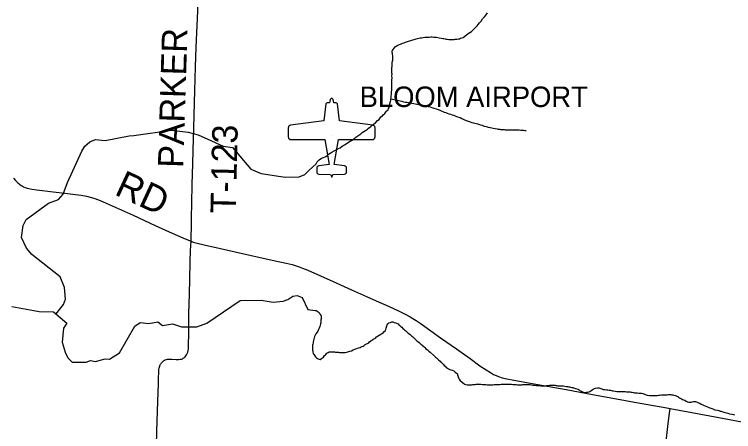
# Model space of a CAD drawing. Extents: x -13.9 to 69.1, y -25.2 to 26.1.
# Drawn here: x 2.896 to 4.329, y 15.614 to 16.445 of the extents above; entities that cross this region are included whole.
import ezdxf

# ---------------------------------------------------------------- set-up
doc = ezdxf.new("R2010")
doc.units = 0
for name, color, linetype in [('GM_X_Airport_Class_3', 7, 'Continuous'), ('GM_X_Airport_Location_Class_3', 7, 'Continuous'), ('GM_X_Airport_Text_Class_3', 7, 'Continuous'), ('GM_X_County_Road', 7, 'Continuous'), ('GM_X_County_Road_Text', 7, 'Continuous'), ('GM_X_Minor_River', 7, 'Continuous'), ('GM_X_Township_Road', 7, 'Continuous'), ('GM_X_Township_Road_Text', 7, 'Continuous')]:
    doc.layers.add(name, color=color, linetype=linetype)

msp = doc.modelspace()

# ---------------------------------------------------------------- linework, layer by layer
at = {"layer": 'GM_X_Airport_Class_3'}
for points in [[(3.5282, 16.2781), (3.5269, 16.2775), (3.5255, 16.2753), (3.5245, 16.272), (3.524, 16.2687), (3.5194, 16.2687), (3.5177, 16.2681), (3.5168, 16.2666), (3.5123, 16.2332), (3.4463, 16.2242), (3.4434, 16.2228), (3.4423, 16.2215), (3.4414, 16.2182), (3.4414, 16.2018), (3.4424, 16.1982), (3.4452, 16.196), (3.5148, 16.1955), (3.5229, 16.1458), (3.5024, 16.1433), (3.5012, 16.143), (3.4994, 16.1413), (3.4989, 16.1401), (3.4987, 16.131), (3.4989, 16.1296), (3.5004, 16.1274), (3.5029, 16.1265), (3.526, 16.1264), (3.5282, 16.1206)], [(3.5282, 16.1206), (3.5304, 16.1264), (3.5535, 16.1265), (3.556, 16.1274), (3.5575, 16.1296), (3.5577, 16.131), (3.5575, 16.1401), (3.557, 16.1413), (3.5551, 16.143), (3.554, 16.1433), (3.5335, 16.1458), (3.5416, 16.1955), (3.6112, 16.196), (3.614, 16.1982), (3.615, 16.2018), (3.615, 16.2182), (3.6141, 16.2215), (3.613, 16.2228), (3.6101, 16.2242), (3.5441, 16.2332), (3.5396, 16.2666), (3.5387, 16.2681), (3.537, 16.2687), (3.5324, 16.2687), (3.5319, 16.272), (3.5309, 16.2753), (3.5295, 16.2775), (3.5282, 16.2781)]]:
    msp.add_lwpolyline(points, dxfattribs=at)
at = {"layer": 'GM_X_Airport_Location_Class_3'}
msp.add_line((3.5282, 16.2037), (3.5282, 16.2037), dxfattribs=at)
at = {"layer": 'GM_X_County_Road'}
for points in [[(2.8942, 16.119), (2.8984, 16.1143), (2.9033, 16.1096), (2.9065, 16.1066), (2.9096, 16.1042), (2.9123, 16.1026), (2.9145, 16.1014), (2.9178, 16.1001), (2.9215, 16.0988), (2.925, 16.098), (2.9309, 16.0967), (2.9406, 16.0954), (2.9732, 16.0918), (2.9968, 16.0892), (3.0127, 16.0871), (3.0292, 16.0847), (3.0401, 16.0827), (3.0472, 16.0811), (3.0547, 16.0789), (3.0637, 16.0757), (3.073, 16.072), (3.0909, 16.064), (3.1092, 16.0556), (3.1326, 16.045), (3.1769, 16.0249), (3.2105, 16.0096), (3.232, 15.9999), (3.2463, 15.9938), (3.248, 15.9932)], [(3.1791, 15.5865), (3.18, 15.6156), (3.182, 15.6744), (3.183, 15.7095), (3.1834, 15.7226), (3.1836, 15.7309), (3.1839, 15.735), (3.1842, 15.7381), (3.1847, 15.741), (3.1858, 15.745), (3.1868, 15.7472), (3.1875, 15.7487), (3.1885, 15.7501), (3.1895, 15.7515), (3.1907, 15.7528), (3.1919, 15.7539), (3.1934, 15.7552), (3.1951, 15.7563), (3.1966, 15.757), (3.1992, 15.758), (3.2011, 15.7584), (3.2029, 15.7587), (3.2052, 15.7589), (3.2096, 15.7588), (3.2185, 15.7582), (3.2228, 15.7581), (3.2263, 15.7583), (3.229, 15.7588), (3.231, 15.7595), (3.2326, 15.7603), (3.234, 15.7612), (3.2353, 15.7622), (3.2366, 15.7634), (3.238, 15.7651), (3.2393, 15.7671), (3.2406, 15.7697), (3.2415, 15.7725), (3.2423, 15.776), (3.2427, 15.7782), (3.2429, 15.7807), (3.2432, 15.7873), (3.2434, 15.8087), (3.2435, 15.8235), (3.244, 15.8509), (3.2443, 15.8675), (3.2448, 15.8895), (3.2454, 15.9163), (3.2463, 15.9531), (3.2471, 15.9751), (3.248, 15.9932)], [(3.248, 15.9932), (3.252, 15.9917), (3.2605, 15.9894), (3.274, 15.9861), (3.307, 15.9788), (3.3655, 15.9657), (3.4158, 15.9544), (3.4375, 15.9498), (3.4494, 15.9468), (3.4574, 15.9445), (3.4632, 15.9426), (3.4701, 15.94), (3.4809, 15.9354), (3.5309, 15.913), (3.5676, 15.8965), (3.5977, 15.883), (3.6171, 15.8744), (3.6427, 15.8631), (3.6625, 15.854), (3.6762, 15.8474), (3.6846, 15.8429), (3.69, 15.8398), (3.6962, 15.8358), (3.7065, 15.8288), (3.7452, 15.8012), (3.7766, 15.7789), (3.8038, 15.7596), (3.8235, 15.7453), (3.8357, 15.7371), (3.8443, 15.7318), (3.8506, 15.7283), (3.8556, 15.7259), (3.8607, 15.7238), (3.8681, 15.7214), (3.8772, 15.7192), (3.8913, 15.7166), (3.9388, 15.708), (3.995, 15.6982), (4.0478, 15.6884), (4.0958, 15.6797), (4.1317, 15.6732), (4.1961, 15.6617), (4.2024, 15.6605)], [(4.1947, 15.5947), (4.1979, 15.6246), (4.2005, 15.6464), (4.2018, 15.6559), (4.2024, 15.6605)], [(4.2024, 15.6605), (4.2636, 15.6494), (4.317, 15.6394), (4.3382, 15.6355), (4.3562, 15.6321), (4.3666, 15.6305), (4.3784, 15.6293)]]:
    msp.add_lwpolyline(points, dxfattribs=at)
at = {"layer": 'GM_X_Minor_River'}
for points in [[(3.6696, 16.3878), (3.6723, 16.3884), (3.675, 16.3895), (3.6774, 16.3902), (3.6795, 16.3909), (3.6815, 16.3916), (3.6839, 16.3923), (3.6859, 16.393), (3.6879, 16.3933), (3.6899, 16.3941), (3.6923, 16.3947), (3.6943, 16.3955), (3.6967, 16.3962), (3.6991, 16.3969), (3.7015, 16.3972), (3.7042, 16.3979), (3.7072, 16.3982), (3.7102, 16.3985), (3.7136, 16.3992), (3.7184, 16.3995), (3.7221, 16.3995), (3.7254, 16.3998), (3.7285, 16.3998), (3.7315, 16.3997), (3.7342, 16.3997), (3.7369, 16.3993), (3.7396, 16.3989), (3.7426, 16.3981), (3.746, 16.3974), (3.7494, 16.397), (3.7517, 16.3966), (3.7544, 16.3962), (3.7565, 16.3958), (3.7585, 16.3958), (3.7619, 16.395), (3.7642, 16.395), (3.7673, 16.3949), (3.77, 16.3949), (3.772, 16.3949), (3.774, 16.3952), (3.7757, 16.3952), (3.7777, 16.3955), (3.7808, 16.3959), (3.7831, 16.3962), (3.7848, 16.3973), (3.7875, 16.398), (3.7899, 16.3987), (3.796, 16.4037), (3.8001, 16.4065), (3.8035, 16.4087), (3.8066, 16.4108), (3.8093, 16.4137), (3.8124, 16.4166), (3.8151, 16.4191), (3.8178, 16.422), (3.8202, 16.4248), (3.8226, 16.4277), (3.8257, 16.4313), (3.8284, 16.436), (3.8328, 16.44), (3.8356, 16.4439), (3.8383, 16.4479)], [(3.483, 16.1344), (3.4975, 16.1476), (3.4992, 16.1516), (3.5019, 16.1538), (3.5036, 16.1556), (3.5077, 16.1584), (3.5121, 16.1602), (3.5152, 16.1612), (3.5169, 16.162), (3.5189, 16.1637), (3.5216, 16.1663), (3.525, 16.1684), (3.5284, 16.1709), (3.5332, 16.1734), (3.5369, 16.1755), (3.54, 16.1769), (3.542, 16.1777), (3.545, 16.1794), (3.5488, 16.1823), (3.5512, 16.1837), (3.5539, 16.1855), (3.5569, 16.1873), (3.5597, 16.1891), (3.5651, 16.1923), (3.5675, 16.1941), (3.5702, 16.1959), (3.5726, 16.1973), (3.5746, 16.1987), (3.5763, 16.2001), (3.5783, 16.2016), (3.5804, 16.203), (3.5821, 16.2041), (3.5845, 16.2055), (3.5862, 16.2073), (3.5889, 16.2094), (3.5923, 16.2116), (3.5957, 16.2137), (3.5977, 16.2148), (3.5994, 16.2166), (3.6015, 16.2184), (3.6042, 16.2205), (3.6062, 16.2216), (3.609, 16.2245), (3.6113, 16.2263), (3.6137, 16.2277), (3.6157, 16.2288), (3.6198, 16.2338), (3.6226, 16.2356), (3.626, 16.2406), (3.6294, 16.2431), (3.6311, 16.2446), (3.6338, 16.2474), (3.6355, 16.2492), (3.6369, 16.2514), (3.6389, 16.2536), (3.6406, 16.255), (3.6417, 16.2575), (3.6424, 16.2593), (3.6427, 16.2615), (3.6452, 16.2713), (3.6459, 16.2742), (3.6463, 16.2764), (3.647, 16.2797), (3.647, 16.2818), (3.6474, 16.2862), (3.6474, 16.2898), (3.6478, 16.2946), (3.6482, 16.2989), (3.6482, 16.3033), (3.6482, 16.3069), (3.6483, 16.3109), (3.6483, 16.3138), (3.6484, 16.3186), (3.6481, 16.3222), (3.6484, 16.3255), (3.6481, 16.3276), (3.6481, 16.3306), (3.6482, 16.3331), (3.6482, 16.336), (3.6482, 16.3389), (3.6486, 16.3411), (3.6486, 16.3436), (3.649, 16.3455), (3.649, 16.3495), (3.6497, 16.3534), (3.6497, 16.356), (3.6498, 16.3578), (3.6498, 16.36), (3.6498, 16.3625), (3.6495, 16.3647), (3.6492, 16.3669), (3.6489, 16.3691), (3.6489, 16.3713), (3.6492, 16.3731), (3.6506, 16.3749), (3.6527, 16.3778), (3.6547, 16.3799), (3.6564, 16.3817), (3.6588, 16.3832), (3.6669, 16.3863), (3.6696, 16.3878)], [(3.6463, 16.2764), (3.6682, 16.2718), (3.6715, 16.271), (3.6745, 16.2702), (3.6776, 16.2698), (3.681, 16.2694), (3.6843, 16.269), (3.688, 16.2682), (3.6921, 16.2675), (3.6981, 16.2663), (3.7029, 16.2655), (3.7066, 16.2644), (3.7103, 16.2636), (3.714, 16.2628), (3.7173, 16.2621), (3.7207, 16.2617), (3.7241, 16.2609), (3.7278, 16.2598), (3.7318, 16.2583), (3.7362, 16.2568), (3.7422, 16.2545), (3.7463, 16.253), (3.7496, 16.2515), (3.7523, 16.2504), (3.7554, 16.2492), (3.758, 16.2481), (3.7614, 16.247), (3.7648, 16.2462), (3.7681, 16.2451), (3.7715, 16.244), (3.7752, 16.2425), (3.7789, 16.241), (3.7839, 16.2394), (3.7876, 16.2376), (3.7917, 16.2357), (3.796, 16.2335), (3.8001, 16.232), (3.8041, 16.2308), (3.8075, 16.2297), (3.8105, 16.2289), (3.8132, 16.2285), (3.8159, 16.2278), (3.8193, 16.2267), (3.824, 16.2251), (3.828, 16.224), (3.8317, 16.2225), (3.8358, 16.2214), (3.8398, 16.2206), (3.8438, 16.2198), (3.8472, 16.2187), (3.8502, 16.2183), (3.8576, 16.2167), (3.86, 16.2163), (3.863, 16.2163), (3.8647, 16.2159), (3.8667, 16.2155), (3.8691, 16.2155), (3.8715, 16.2155), (3.8735, 16.2151), (3.8755, 16.2151), (3.8775, 16.215), (3.8796, 16.215), (3.8823, 16.215), (3.8853, 16.2149), (3.8894, 16.2149), (3.8927, 16.2149), (3.8958, 16.2148), (3.8988, 16.2148), (3.9015, 16.2147), (3.9049, 16.2143), (3.9076, 16.2143), (3.9106, 16.2143), (3.913, 16.2139), (3.9147, 16.2139), (3.9157, 16.2138)], [(2.9792, 15.8486), (2.9938, 15.8674), (2.9977, 15.8782), (2.9963, 15.9015), (2.9872, 15.9227), (2.9308, 15.9668), (2.9202, 15.9794), (2.9107, 16.0006), (2.9137, 16.0245), (2.92, 16.0368), (2.9643, 16.0691), (2.9843, 16.0764), (2.9932, 16.0872), (3.002, 16.1103), (3.0305, 16.1723), (3.0364, 16.1827), (3.0466, 16.1913), (3.0575, 16.1955), (3.0767, 16.1937), (3.1247, 16.2034), (3.1342, 16.2036), (3.2089, 16.2144), (3.2422, 16.2106), (3.2624, 16.2052), (3.2815, 16.1962), (3.312, 16.1826), (3.3305, 16.1801), (3.367, 16.137), (3.3875, 16.1283), (3.4269, 16.1219), (3.4359, 16.121), (3.4636, 16.1213), (3.4745, 16.1262), (3.483, 16.1344)], [(2.8909, 15.8636), (2.9349, 15.8552), (2.9454, 15.8536), (2.9744, 15.8528), (3.0007, 15.8302), (2.9941, 15.8205), (2.9914, 15.7922), (2.9972, 15.7725), (3.0027, 15.7615), (3.0114, 15.7526), (3.0394, 15.7526), (3.0479, 15.7557), (3.058, 15.7537), (3.0773, 15.7592), (3.0857, 15.7587), (3.1054, 15.7715), (3.1359, 15.824), (3.1468, 15.8318), (3.1643, 15.8297), (3.1822, 15.8331), (3.1909, 15.8256), (3.2112, 15.8286), (3.229, 15.8232), (3.2593, 15.8231), (3.2793, 15.8304), (3.3458, 15.8754), (3.3879, 15.8762), (3.4118, 15.8722), (3.4318, 15.8737), (3.4409, 15.8775), (3.4508, 15.8843), (3.4596, 15.8856), (3.4696, 15.881), (3.4808, 15.8573)], [(3.4808, 15.8573), (3.4953, 15.8556), (3.4976, 15.8553), (3.503, 15.8516), (3.5053, 15.8472), (3.507, 15.8446), (3.5076, 15.842), (3.5073, 15.8391), (3.5069, 15.8366), (3.5065, 15.833), (3.5065, 15.8308), (3.5062, 15.829), (3.5055, 15.8264), (3.5047, 15.8235), (3.5034, 15.8206), (3.502, 15.8174), (3.5006, 15.8145), (3.4992, 15.8123), (3.4968, 15.8091), (3.4955, 15.8062), (3.4941, 15.8037), (3.4934, 15.8011), (3.4927, 15.7986), (3.492, 15.796), (3.4916, 15.7931), (3.4913, 15.791), (3.4909, 15.7884), (3.4902, 15.7866), (3.4902, 15.7844), (3.4901, 15.779), (3.4901, 15.7768), (3.4904, 15.7746), (3.4907, 15.7724), (3.4914, 15.7699), (3.4931, 15.7669), (3.4944, 15.7651), (3.4961, 15.7633), (3.4977, 15.7611), (3.4997, 15.7596), (3.5014, 15.7592), (3.5034, 15.7585), (3.5055, 15.7581), (3.5082, 15.7602), (3.5102, 15.7613), (3.5119, 15.7623), (3.5136, 15.7656), (3.5157, 15.7674), (3.5184, 15.7706), (3.5211, 15.7721), (3.5232, 15.7731), (3.5275, 15.7731), (3.5306, 15.773), (3.5336, 15.773), (3.5356, 15.7726), (3.5387, 15.7726), (3.5417, 15.7722), (3.5437, 15.7721), (3.5458, 15.7718), (3.5478, 15.7717), (3.5501, 15.7717), (3.5525, 15.7717), (3.5549, 15.772), (3.5576, 15.7723), (3.5603, 15.773), (3.5643, 15.7744), (3.5674, 15.7755), (3.5708, 15.7769), (3.5745, 15.7787), (3.5782, 15.7797), (3.5816, 15.7811), (3.5847, 15.7818), (3.587, 15.7829), (3.5891, 15.7836), (3.5911, 15.7847), (3.5928, 15.7857), (3.5949, 15.7875), (3.5976, 15.7889), (3.5996, 15.79), (3.602, 15.7914), (3.6037, 15.7932), (3.6064, 15.795), (3.6084, 15.7961), (3.6105, 15.7979), (3.6125, 15.7989), (3.6152, 15.8007), (3.6176, 15.8029), (3.6197, 15.8043), (3.6258, 15.8082), (3.6285, 15.81), (3.6305, 15.8111), (3.6322, 15.8129), (3.6346, 15.815), (3.636, 15.8176), (3.637, 15.8205), (3.6381, 15.8248), (3.6388, 15.8266), (3.6398, 15.8288), (3.6422, 15.831), (3.6452, 15.8316), (3.6483, 15.8327), (3.65, 15.8327)], [(3.65, 15.8327), (3.653, 15.8316), (3.656, 15.8308), (3.6587, 15.8297), (3.6604, 15.8286), (3.6621, 15.8271), (3.6638, 15.8256), (3.6658, 15.8238), (3.6681, 15.8223), (3.6698, 15.8197), (3.6721, 15.8182), (3.6738, 15.8164), (3.6758, 15.8149), (3.6778, 15.8131), (3.6802, 15.8112), (3.6822, 15.8094), (3.6845, 15.8075), (3.6862, 15.8064), (3.6882, 15.8046), (3.6899, 15.8031), (3.6935, 15.7994), (3.6959, 15.7972), (3.6979, 15.7954), (3.6999, 15.7935), (3.7022, 15.7917), (3.7039, 15.7902), (3.7059, 15.7887), (3.7076, 15.7873), (3.7093, 15.7858), (3.7116, 15.7836), (3.714, 15.7821), (3.716, 15.7791), (3.7193, 15.7773), (3.7216, 15.7747), (3.7243, 15.7725), (3.7314, 15.7662), (3.733, 15.7644), (3.735, 15.7629), (3.7367, 15.7611), (3.7387, 15.7592), (3.7407, 15.757), (3.7441, 15.7544), (3.7461, 15.7522), (3.7477, 15.7511), (3.7507, 15.7478), (3.7524, 15.746), (3.7541, 15.7445), (3.7564, 15.7423), (3.7588, 15.7408), (3.7611, 15.7393), (3.7638, 15.7378), (3.7658, 15.7374), (3.7685, 15.7367), (3.7712, 15.7352), (3.7742, 15.733), (3.7766, 15.7308), (3.7789, 15.7293), (3.7789, 15.7271), (3.7802, 15.7231), (3.7809, 15.7213), (3.7822, 15.7187), (3.7835, 15.7165), (3.7885, 15.7121), (3.7912, 15.7102), (3.7929, 15.7091), (3.7956, 15.708), (3.7979, 15.7072), (3.8006, 15.7072), (3.8027, 15.7072), (3.8057, 15.7075), (3.8077, 15.7078), (3.8094, 15.7082), (3.8125, 15.7085), (3.8142, 15.7085), (3.8162, 15.7088), (3.8189, 15.7088), (3.8206, 15.7088), (3.8229, 15.7088), (3.8256, 15.7087), (3.8283, 15.7083), (3.83, 15.7083), (3.8327, 15.7083), (3.8351, 15.7079), (3.8378, 15.7075), (3.8401, 15.7075), (3.8439, 15.7078), (3.8469, 15.7077), (3.8493, 15.7077), (3.8516, 15.708), (3.8543, 15.708), (3.8604, 15.7083), (3.8634, 15.7083), (3.8655, 15.7086), (3.8672, 15.7086), (3.8709, 15.7089), (3.8726, 15.7089), (3.8753, 15.7088), (3.8776, 15.7088), (3.88, 15.7088), (3.882, 15.7088), (3.8847, 15.7087)], [(3.8847, 15.7087), (3.8867, 15.7087), (3.8888, 15.7083), (3.8904, 15.7083), (3.8931, 15.7079), (3.8958, 15.7079), (3.8982, 15.7078), (3.9006, 15.7078), (3.9033, 15.7078), (3.9053, 15.7078), (3.9073, 15.7077), (3.909, 15.7081), (3.9107, 15.7084), (3.9127, 15.7084), (3.9147, 15.7084), (3.9164, 15.7083), (3.9191, 15.7083), (3.9222, 15.7079), (3.9239, 15.7079), (3.9259, 15.7075), (3.9286, 15.7071), (3.9319, 15.7067), (3.9356, 15.7063), (3.938, 15.7059), (3.94, 15.7059), (3.9421, 15.7059), (3.9451, 15.7055), (3.9475, 15.7051), (3.9502, 15.7054), (3.9525, 15.7054), (3.9545, 15.7057), (3.9566, 15.706), (3.9586, 15.706), (3.961, 15.7064), (3.9627, 15.7067), (3.965, 15.7067), (3.9694, 15.707), (3.9711, 15.707), (3.9731, 15.7066), (3.9748, 15.7065), (3.9765, 15.7062), (3.9785, 15.7058), (3.9805, 15.7058), (3.9829, 15.7054), (3.9856, 15.7053), (3.9876, 15.7053), (3.9896, 15.7053), (3.9927, 15.7049), (3.9954, 15.7045), (3.9977, 15.7041), (3.9998, 15.7037), (4.0018, 15.7033), (4.0041, 15.7029), (4.0065, 15.7025), (4.0085, 15.7021), (4.0102, 15.7018), (4.0122, 15.701), (4.0142, 15.7003), (4.0163, 15.6995), (4.0189, 15.6987), (4.021, 15.6973), (4.0233, 15.6958), (4.026, 15.6947), (4.028, 15.6935), (4.0307, 15.6928), (4.0337, 15.6924), (4.0358, 15.6927), (4.0378, 15.6931), (4.0408, 15.6937), (4.0425, 15.6941), (4.0446, 15.6955), (4.047, 15.6973), (4.0493, 15.6987), (4.052, 15.7002), (4.0537, 15.7009), (4.0575, 15.7015), (4.0602, 15.7015), (4.0662, 15.6993), (4.0689, 15.6985), (4.0726, 15.6981), (4.0753, 15.6977), (4.0783, 15.6973), (4.081, 15.6969), (4.0834, 15.6969), (4.0854, 15.6965), (4.0874, 15.6957), (4.0898, 15.6953), (4.0932, 15.6949), (4.0965, 15.6942), (4.0992, 15.6941), (4.1016, 15.6941), (4.1046, 15.6941), (4.107, 15.694), (4.1097, 15.6944), (4.1127, 15.6943), (4.1154, 15.6939), (4.1175, 15.6939), (4.1192, 15.6939), (4.1208, 15.6939), (4.1225, 15.6935), (4.1245, 15.6931)], [(4.1245, 15.6931), (4.1266, 15.6927), (4.1293, 15.6923), (4.1316, 15.6919), (4.1343, 15.6919), (4.137, 15.6915), (4.1401, 15.6911), (4.1431, 15.6907), (4.1454, 15.6907), (4.1478, 15.6903), (4.1498, 15.6895), (4.1529, 15.6884), (4.1569, 15.6872), (4.1613, 15.6865), (4.164, 15.6861), (4.1663, 15.686), (4.168, 15.686), (4.1697, 15.686), (4.1717, 15.686), (4.1741, 15.6863), (4.1765, 15.6866), (4.1795, 15.687), (4.1819, 15.6869), (4.1852, 15.6873), (4.1876, 15.6876), (4.1913, 15.6876), (4.1944, 15.6879), (4.1964, 15.6879), (4.1988, 15.6882), (4.2004, 15.6882), (4.2031, 15.6881), (4.2052, 15.6878), (4.2075, 15.6874), (4.2099, 15.687), (4.2122, 15.6862), (4.2143, 15.6855), (4.2159, 15.6847), (4.2176, 15.6843), (4.2193, 15.6829), (4.2213, 15.6817), (4.2247, 15.6799), (4.2267, 15.6784), (4.2287, 15.6777), (4.2314, 15.6769), (4.2341, 15.6747), (4.2368, 15.6736), (4.2398, 15.6728), (4.2425, 15.6731), (4.2442, 15.6731), (4.2462, 15.6738), (4.2489, 15.6741), (4.2509, 15.6741), (4.2526, 15.6745), (4.2546, 15.6737), (4.259, 15.6718), (4.2617, 15.6707), (4.2644, 15.6692), (4.2674, 15.6677), (4.2701, 15.6666), (4.2765, 15.6636), (4.2795, 15.6625), (4.2832, 15.661), (4.2872, 15.6595), (4.2913, 15.658), (4.2967, 15.6568), (4.2997, 15.6561), (4.3021, 15.6553), (4.3041, 15.6549), (4.3074, 15.6538), (4.3095, 15.653), (4.3118, 15.6523), (4.3145, 15.6515), (4.3172, 15.6508), (4.3206, 15.65), (4.3256, 15.6488), (4.3283, 15.6484), (4.3307, 15.6477)]]:
    msp.add_lwpolyline(points, dxfattribs=at)
at = {"layer": 'GM_X_Township_Road'}
msp.add_lwpolyline([(3.248, 15.9932), (3.2481, 15.9999), (3.2487, 16.0249), (3.2491, 16.0398), (3.2497, 16.0689), (3.2506, 16.1064), (3.2515, 16.1474), (3.2524, 16.1747), (3.2535, 16.2181), (3.255, 16.2692), (3.2556, 16.2924), (3.257, 16.3406), (3.2585, 16.3786), (3.2596, 16.4089), (3.2607, 16.4369), (3.2636, 16.4975)], dxfattribs=at)

# ---------------------------------------------------------------- texts
at = {"layer": 'GM_X_Airport_Text_Class_3'}
msp.add_text('BLOOM AIRPORT', height=0.040788, rotation=0, dxfattribs=at).set_placement((3.5839, 16.2604))
at = {"layer": 'GM_X_County_Road_Text'}
msp.add_text('RD', height=0.0538, rotation=335.1784, dxfattribs=at).set_placement((3.0935, 16.087))
at = {"layer": 'GM_X_Township_Road_Text'}
for s, rotation, p in [('PARKER', 88.2304, (3.2325, 16.1388)), ('T-123', 88.7082, (3.3372, 16.0483))]:
    msp.add_text(s, height=0.05055, rotation=rotation, dxfattribs=at).set_placement(p)

doc.saveas('drawing.dxf')
